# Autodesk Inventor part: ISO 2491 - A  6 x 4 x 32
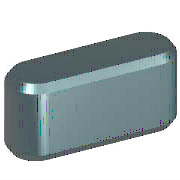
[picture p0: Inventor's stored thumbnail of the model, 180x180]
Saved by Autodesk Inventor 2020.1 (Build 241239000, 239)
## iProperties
Created: 2019-01
Part Number: ISO 2491 - A  6 x 4 x 32
Material: Stahl, weich
Description: Passfedern
Document SubType Name: Modeling
Standard: ISO 2491
Designer: lutzd
Standard Revision: First edition 1974-08-15
Standards Organization: ISO
Language: de-DE
Size Designation: A  6 x 4 x 32
Categories: <MemberInstance><Categories><Category DisplayName="Wellenteile" InternalName="7f7aeb1f-a693-4053-b835-cee3144e0d98" Mnemonic="SHFT"><Category DisplayName="Passf
Mass: 5.69828 g
Surface Area: 6.18328 cm^2
Volume: 0.725895 cm^3
Density: 7.85 g/cm^3
Appearance: Halbpoliert
IsCustomPart: 0
Author: lutzd
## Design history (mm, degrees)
workplane "Work Plane1"
workplane "Work Plane2"
sketch "Skizze1"
  geometry: L1 (3, 3)-(29, 3); L2 (29, -3)-(3, -3); L3 (0, 9.4)-(0, -7.4) reference; L4 (-5, 0)-(30, 0) reference; L5 (32, 0)-(32, 7); A1 r 3 centre (3, 0) between (3, 3) and (3, -3); A2 r 3 centre (29, 0) between (29, -3) and (29, 3)
  constraints: 6 end point, 5 point on circle, 4 tangent, 3 point on line, 2 centre point, 1 horizontal, 1 parallel, 1 perpendicular
  dimensions: "d0" = 3 radius of A1 (= 0.5 x PB); "d13" = 3 radius of A2 (= 0.5 x PB); "d14" = 32 distance between parallel lines of L5 L3 (= NLG)
extrude "Körper1" new body sketch "Skizze1" taper "d3" = 0 deg; stored distance "d4" = 10
workplane "Work Plane3"
body "Solid1"
chamfer "Fase1" distance "d8" = 0.4 (= PHH); stored, may be unused: second distance "d9" = 0.4 (= PHH), angle "d15" = 45 deg
other parameters: "d1" = -2.5 (= -PNT), "d2" = 1.5 (= PH - PNT), "NLG" = 32 [user parameter; used in 1 equation term], "PB" = 6 [user parameter; used in 2 equation terms], "PNT" = 2.5 [user parameter; used in 2 equation terms], "PH" = 4 [user parameter; used in 1 equation term], "PHH" = 0.4 [user parameter; used in 2 equation terms], "d10" = 0, "d16" = 0, "d17" = 0, "d18" = 0, "RR" = 0.16 [user parameter], "WDMIN" = 17 [user parameter], "WDMAX" = 22 [user parameter], "PLB1" = 32 [user parameter], "PLB2" = 32 [user parameter], "PUEB" = 1.8 [user parameter]
